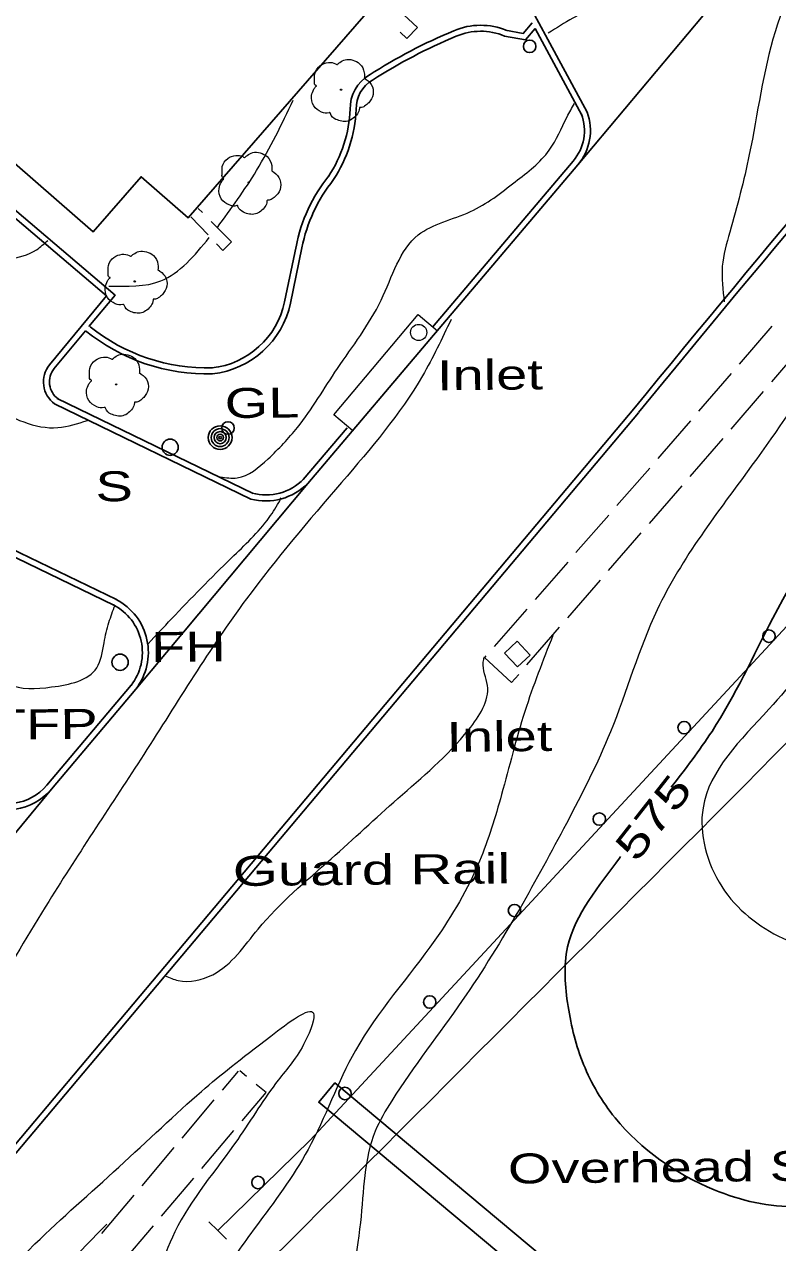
# Model space of a CAD drawing. Extents: x 2361708 to 2370558, y 6977955 to 6991887.
# Drawn here: x 2368899.2 to 2369020, y 6990434.2 to 6990629.5 of the extents above; entities that cross this region are included whole.
import ezdxf
from ezdxf.enums import TextEntityAlignment as Align

# ---------------------------------------------------------------- set-up
doc = ezdxf.new("R2010")
doc.units = 0
doc.header["$LTSCALE"] = 1.9
for name, color, linetype, lineweight in [('11', 7, 'Continuous', 25), ('2', 7, 'Continuous', 25), ('20', 7, 'Continuous', 25), ('21', 7, 'Continuous', 25), ('23', 7, 'Continuous', 25), ('28', 7, 'Continuous', 13), ('29', 7, 'Continuous', 13), ('31', 7, 'Continuous', 13), ('35', 7, 'Continuous', 13), ('4', 7, 'Continuous', 25), ('7', 7, 'Continuous', 25), ('9', 7, 'Continuous', 13)]:
    doc.layers.add(name, color=color, linetype=linetype, lineweight=lineweight)

msp = doc.modelspace()

# ---------------------------------------------------------------- linework, layer by layer
at = {"layer": '11'}
msp.add_lwpolyline([(2368803.061, 6990680.605), (2368887.263, 6990607.323), (2368891.675, 6990612.405), (2368910.239, 6990596.271), (2368917.905, 6990605.094), (2368925.478, 6990598.516), (2368956.5, 6990634.183), (2368949.038, 6990640.673), (2368978.25, 6990674.242), (2368958.133, 6990691.742), (2368936.419, 6990666.784), (2368928.906, 6990673.312), (2368921.191, 6990664.449), (2368845.954, 6990729.906)], close=True, dxfattribs=at)
at = {"layer": '2'}
for p, q in [((2369017.971, 6990642.809), (2368987.911, 6990606.981)), ((2368988.565, 6990614.987), (2368981.082, 6990628.857)), ((2368964.627, 6990580.988), (2368987.175, 6990607.604)), ((2368944.655, 6990555.917), (2368987.911, 6990606.981)), ((2368940.927, 6990585.003), (2368942.763, 6990593.88)), ((2368941.869, 6990584.811), (2368943.705, 6990593.69)), ((2368908.99, 6990580.369), (2368903.958, 6990574.301)), ((2368904.041, 6990568.681), (2368935.488, 6990553.41)), ((2368904.463, 6990569.545), (2368935.91, 6990554.273)), ((2368943.919, 6990556.54), (2368950.96, 6990564.847)), ((2368944.655, 6990555.917), (2368917.077, 6990522.933)), ((2368902.813, 6990507.516), (2368916.341, 6990523.556)), ((2368903.549, 6990506.893), (2368917.077, 6990522.933)), ((2368903.549, 6990506.893), (2368874.918, 6990472.179))]:
    msp.add_line(p, q, dxfattribs=at)
for points in [[(2368989.41, 6990615.446), (2368975.362, 6990641.493), (2368960.799, 6990654.315)], [(2368976.184, 6990627.65), (2368979.55, 6990627.032), (2368981.082, 6990628.857)], [(2368976.354, 6990628.592), (2368979.17, 6990628.079), (2368980.594, 6990629.772)], [(2368887.263, 6990607.323), (2368912.397, 6990585.981), (2368903.222, 6990574.913)], [(2368887.886, 6990608.059), (2368913.746, 6990586.094), (2368909.564, 6990581.064)], [(2368913.951, 6990537.274), (2368882.916, 6990552.269), (2368824.074, 6990603.741), (2368711.364, 6990604.229), (2368623.522, 6990603.912)], [(2368913.529, 6990536.41), (2368882.384, 6990551.464), (2368823.713, 6990602.788), (2368711.363, 6990603.268), (2368623.522, 6990602.952)], [(2368996.914, 6990567.865), (2368920.861, 6990477.417), (2368836.413, 6990376.958), (2368777.799, 6990307.707)], [(2368997.649, 6990567.252), (2368921.597, 6990476.803), (2368837.149, 6990376.334), (2368778.535, 6990307.084)]]:
    msp.add_lwpolyline(points, dxfattribs=at)
for centre, radius, start, end in [((2371141.169, 6988819.351), 2766.791, 136.64719, 140.80479), ((2371141.169, 6988819.351), 2765.831, 136.64719, 140.80479), ((2357902.578, 7001481.989), 15617.856, 315.34492, 316.12114), ((2368972.348, 6990618.451), 10.927, 67.36788, 113.12687), ((2369001.889, 6990547.487), 87.793, 112.66125, 122.67503), ((2369001.889, 6990547.487), 86.833, 112.66125, 122.67503), ((2368972.348, 6990618.451), 9.967, 67.36788, 113.12687), ((2368957.64, 6990616.048), 6.198, 120.13581, 181.80231), ((2368957.64, 6990616.048), 5.238, 120.13581, 181.80231), ((2368929.835, 6990616.938), 21.634, 326.98799, 357.32491), ((2368929.835, 6990616.938), 22.594, 326.98799, 357.32491), ((2368981.547, 6990612.473), 7.446, 319.20201, 20.70764), ((2368981.547, 6990612.473), 8.406, 319.20201, 20.70764), ((2368968.269, 6990588.937), 25.98, 141.16065, 169.05106), ((2368968.269, 6990588.937), 25.02, 141.16065, 169.05106), ((2368927.746, 6990587.819), 13.48, 276.52498, 347.98131), ((2368927.746, 6990587.819), 14.44, 276.52498, 347.98131), ((2368928.518, 6990604.328), 30.867, 230.83015, 271.61276), ((2368928.518, 6990604.328), 29.907, 231.15155, 271.61276), ((2368906.631, 6990572.191), 4.362, 141.3907, 233.58599), ((2368906.631, 6990572.191), 3.402, 141.3907, 233.58599), ((2368937.894, 6990562.623), 8.562, 255.36713, 315.23427), ((2368937.894, 6990562.623), 9.522, 255.36713, 315.23427), ((2368909.514, 6990528.795), 9.569, 322.21872, 62.37943), ((2368909.514, 6990528.795), 8.609, 322.21872, 62.37943), ((2368896.438, 6990512.877), 8.333, 236.84602, 319.91801), ((2368896.438, 6990512.877), 9.293, 236.84602, 319.91801), ((2318071.367, 7041248.644), 71901.899, 314.92877, 315.1113)]:
    msp.add_arc(centre, radius, start, end, dxfattribs=at)
at = {"layer": '20'}
for centre, radius in [((2368930.594, 6990563.253), 1.9), ((2368930.594, 6990563.253), 1.442), ((2368930.594, 6990563.253), 0.973), ((2368931.85, 6990564.785), 1), ((2368930.594, 6990563.253), 0.539), ((2368930.594, 6990563.253), 0.192), ((2368914.556, 6990527.229), 1.3)]:
    msp.add_circle(centre, radius, dxfattribs=at)
at = {"layer": '21'}
msp.add_circle((2368922.579, 6990561.707), 1.3, dxfattribs=at)
at = {"layer": '23'}
msp.add_circle((2368980.209, 6990625.999), 1, dxfattribs=at)
at = {"layer": '28'}
for p, q in [((2368927.741, 6990599.328), (2368927.094, 6990599.982)), ((2368925.877, 6990598.64), (2368928.645, 6990595.756)), ((2369019.038, 6990581.106), (2369013.816, 6990575.046)), ((2369019.013, 6990572.195), (2369024.216, 6990578.265)), ((2369012.51, 6990573.534), (2369007.288, 6990567.474)), ((2369012.505, 6990564.603), (2369017.708, 6990570.673)), ((2369005.957, 6990557.04), (2369011.2, 6990563.09)), ((2368999.454, 6990558.379), (2368994.201, 6990552.348)), ((2368999.408, 6990549.487), (2369004.651, 6990555.528)), ((2368992.885, 6990550.836), (2368987.633, 6990544.805)), ((2368992.86, 6990541.925), (2368998.103, 6990547.975)), ((2368986.317, 6990543.303), (2368981.064, 6990537.273)), ((2368986.312, 6990534.362), (2368991.555, 6990540.412)), ((2368979.749, 6990535.769), (2368974.495, 6990529.74)), ((2368979.774, 6990526.8), (2368985.006, 6990532.85)), ((2368933.461, 6990461.655), (2368930.89, 6990458.591)), ((2368934.83, 6990460.799), (2368933.751, 6990461.698)), ((2368929.605, 6990457.059), (2368924.453, 6990450.939)), ((2368927.65, 6990446.039), (2368932.812, 6990452.149)), ((2368923.167, 6990449.407), (2368918.015, 6990443.288)), ((2368921.202, 6990438.398), (2368926.364, 6990444.507)), ((2368916.73, 6990441.755), (2368911.578, 6990435.636)), ((2368914.745, 6990430.756), (2368919.907, 6990436.866))]:
    msp.add_line(p, q, dxfattribs=at)
for points in [[(2368959.437, 6990628.271), (2368960.517, 6990627.231), (2368962.25, 6990628.998), (2368959.304, 6990631.74)], [(2368930.029, 6990594.31), (2368931.039, 6990593.259), (2368932.395, 6990594.662), (2368929.154, 6990597.911)], [(2369005.982, 6990565.961), (2369001.413, 6990560.637), (2369000.77, 6990559.891)], [(2368973.18, 6990528.237), (2368972.972, 6990527.995), (2368977.32, 6990523.966), (2368978.468, 6990525.287)], [(2368934.107, 6990453.672), (2368937.944, 6990458.218), (2368936.362, 6990459.523)]]:
    msp.add_lwpolyline(points, dxfattribs=at)
at = {"layer": '29'}
for centre in [(2368949.974, 6990619.05), (2368935.155, 6990604.159), (2368916.905, 6990588.304), (2368913.922, 6990571.795)]:
    msp.add_circle(centre, 0.1, dxfattribs=at)
for points in [[(2368946.008, 6990619.623), (2368946.028, 6990619.633), (2368945.948, 6990619.702), (2368945.712, 6990620.33), (2368945.75, 6990621.61), (2368946.637, 6990622.909), (2368947.943, 6990623.392), (2368949.064, 6990623.202), (2368949.296, 6990623.074), (2368949.366, 6990623.075), (2368949.415, 6990623.115), (2368949.763, 6990623.409), (2368950.629, 6990623.857), (2368951.839, 6990623.789), (2368952.955, 6990623.199), (2368953.688, 6990621.776), (2368953.696, 6990620.916)], [(2368953.686, 6990620.936), (2368954.826, 6990619.877), (2368955.111, 6990618.289), (2368954.404, 6990616.963), (2368953.75, 6990616.416), (2368953.081, 6990616.2), (2368952.931, 6990616.189), (2368952.912, 6990616.078), (2368952.591, 6990615.175), (2368951.052, 6990614.01), (2368949.159, 6990614.293), (2368948.26, 6990615.234), (2368948.189, 6990615.363), (2368948.069, 6990615.342), (2368946.858, 6990615.461), (2368945.589, 6990616.459), (2368945.243, 6990618.095), (2368945.613, 6990619.119), (2368945.939, 6990619.562), (2368946.008, 6990619.613)], [(2368931.189, 6990604.731), (2368931.209, 6990604.741), (2368931.129, 6990604.81), (2368930.893, 6990605.438), (2368930.931, 6990606.718), (2368931.818, 6990608.017), (2368933.123, 6990608.5), (2368934.245, 6990608.31), (2368934.477, 6990608.182), (2368934.547, 6990608.183), (2368934.596, 6990608.223), (2368934.944, 6990608.517), (2368935.809, 6990608.966), (2368937.02, 6990608.897), (2368938.136, 6990608.307), (2368938.869, 6990606.884), (2368938.878, 6990606.024)], [(2368938.867, 6990606.044), (2368940.007, 6990604.985), (2368940.292, 6990603.398), (2368939.585, 6990602.071), (2368938.93, 6990601.525), (2368938.262, 6990601.308), (2368938.112, 6990601.296), (2368938.093, 6990601.186), (2368937.772, 6990600.283), (2368936.233, 6990599.119), (2368934.34, 6990599.401), (2368933.441, 6990600.342), (2368933.37, 6990600.471), (2368933.25, 6990600.45), (2368932.039, 6990600.569), (2368930.77, 6990601.567), (2368930.424, 6990603.204), (2368930.794, 6990604.227), (2368931.12, 6990604.67), (2368931.19, 6990604.721)], [(2368912.939, 6990588.876), (2368912.959, 6990588.887), (2368912.879, 6990588.956), (2368912.642, 6990589.584), (2368912.68, 6990590.864), (2368913.569, 6990592.162), (2368914.874, 6990592.645), (2368915.995, 6990592.456), (2368916.227, 6990592.328), (2368916.297, 6990592.328), (2368916.346, 6990592.369), (2368916.694, 6990592.662), (2368917.559, 6990593.111), (2368918.77, 6990593.042), (2368919.885, 6990592.452), (2368920.619, 6990591.03), (2368920.628, 6990590.17)], [(2368920.617, 6990590.19), (2368921.758, 6990589.13), (2368922.043, 6990587.543), (2368921.335, 6990586.216), (2368920.68, 6990585.67), (2368920.012, 6990585.453), (2368919.862, 6990585.442), (2368919.843, 6990585.332), (2368919.522, 6990584.429), (2368917.983, 6990583.264), (2368916.091, 6990583.546), (2368915.191, 6990584.488), (2368915.12, 6990584.617), (2368915, 6990584.596), (2368913.789, 6990584.714), (2368912.52, 6990585.712), (2368912.174, 6990587.349), (2368912.544, 6990588.373), (2368912.87, 6990588.816), (2368912.939, 6990588.866)], [(2368909.956, 6990572.367), (2368909.976, 6990572.377), (2368909.896, 6990572.447), (2368909.66, 6990573.075), (2368909.698, 6990574.355), (2368910.585, 6990575.653), (2368911.89, 6990576.136), (2368913.012, 6990575.947), (2368913.244, 6990575.819), (2368913.314, 6990575.819), (2368913.364, 6990575.86), (2368913.711, 6990576.153), (2368914.576, 6990576.601), (2368915.787, 6990576.533), (2368916.903, 6990575.944), (2368917.636, 6990574.521), (2368917.645, 6990573.661)], [(2368917.634, 6990573.68), (2368918.774, 6990572.621), (2368919.059, 6990571.034), (2368918.352, 6990569.707), (2368917.697, 6990569.161), (2368917.03, 6990568.944), (2368916.88, 6990568.933), (2368916.861, 6990568.823), (2368916.539, 6990567.92), (2368915, 6990566.755), (2368913.107, 6990567.037), (2368912.208, 6990567.978), (2368912.137, 6990568.108), (2368912.017, 6990568.087), (2368910.806, 6990568.205), (2368909.536, 6990569.203), (2368909.191, 6990570.84), (2368909.561, 6990571.863), (2368909.887, 6990572.306), (2368909.957, 6990572.357)]]:
    msp.add_spline(points, degree=3, dxfattribs=at)
at = {"layer": '31', "lineweight": 25}
for points in [[(2369088.686, 6990644.742), (2369081.491, 6990634.793), (2369067.406, 6990613.188), (2369047.405, 6990584.746), (2369032.432, 6990557.712), (2369019.194, 6990534.305), (2369009.436, 6990516.152), (2369002.891, 6990507.188)], [(2368994.777, 6990496.071), (2368994.609, 6990495.839), (2368986.294, 6990481.57), (2368986.365, 6990472.05), (2368988.844, 6990462.743), (2368993.896, 6990454.18), (2369009.786, 6990442.641), (2369023.212, 6990439.969), (2369037.171, 6990443.292), (2369051.308, 6990451.057), (2369056.994, 6990453.551), (2369054.972, 6990449.552), (2369049.111, 6990441.285), (2369037.637, 6990424.865), (2369032.644, 6990416.718), (2369033.637, 6990410.067), (2369039.979, 6990406.757), (2369053.742, 6990403.358), (2369071.707, 6990406.089), (2369090.73, 6990421.661)]]:
    msp.add_spline(points, degree=3, dxfattribs=at)
at = {"layer": '35'}
for points in [[(2369142.131, 6990706.454), (2369132.193, 6990693.679), (2369114.461, 6990671.668), (2369095.193, 6990641.974), (2369078.336, 6990617.423), (2369064.55, 6990594.82), (2369047.526, 6990566.837), (2369036.472, 6990545.18), (2369018.533, 6990519.688), (2369007.993, 6990503.897), (2369011.004, 6990491.245), (2369020.812, 6990482.968), (2369042.265, 6990480.742), (2369066.008, 6990491.099), (2369087.776, 6990506.106), (2369108.873, 6990519.168), (2369106.251, 6990510.873), (2369095.056, 6990495.585), (2369090.948, 6990489.106), (2369090.306, 6990480.859), (2369093.96, 6990472.064), (2369100.283, 6990468.664), (2369121.537, 6990484.057), (2369144.566, 6990505.287), (2369169.56, 6990526.086), (2369196.724, 6990548.916), (2369226.46, 6990573.57), (2369250.046, 6990595.115), (2369253.058, 6990598.144)], [(2369061.565, 6990692.036), (2369052.066, 6990680.285), (2369039.281, 6990662.943), (2369028.55, 6990647.22), (2369019.539, 6990628.333), (2369015.416, 6990608.643), (2369012.285, 6990596.212), (2369011.087, 6990590.721), (2369011.411, 6990585.004)], [(2369003.163, 6990643.598), (2368998.971, 6990639.618), (2368994.302, 6990635.243), (2368990.28, 6990632.275), (2368987.137, 6990630.535), (2368983.199, 6990628.107)], [(2368833.891, 6990631.396), (2368840.245, 6990625.727), (2368851.851, 6990613.596), (2368864.177, 6990603.563), (2368878.689, 6990596.101), (2368889.433, 6990592.583), (2368896.65, 6990591.931), (2368901.156, 6990593.384), (2368902.962, 6990594.882)], [(2368800.158, 6990628.425), (2368811.574, 6990626.774), (2368821.308, 6990623.276), (2368828.124, 6990620.591), (2368836.032, 6990616.646), (2368844.735, 6990606.898), (2368856.024, 6990597.515), (2368867.944, 6990584.998), (2368882.904, 6990574.61), (2368893.845, 6990568.264), (2368904.588, 6990564.856), (2368909.347, 6990566.021)], [(2368930.144, 6990596.951), (2368936.437, 6990606.091), (2368942.32, 6990617.378)], [(2368930.614, 6990556.963), (2368933.316, 6990556.799), (2368938.267, 6990559.836), (2368942.979, 6990564.871), (2368949.39, 6990574.323), (2368956.395, 6990585.31), (2368962.336, 6990595.757), (2368970.711, 6990599.497), (2368977.906, 6990604.285), (2368983.358, 6990609.348), (2368986.208, 6990614.685), (2368987.387, 6990616.846)], [(2369047.828, 6990605.451), (2369038.394, 6990593.231), (2369027.418, 6990575.906), (2369015.841, 6990558.825), (2369000.65, 6990535.639), (2368993.146, 6990516.056), (2368986.096, 6990501.379), (2368978.606, 6990487.716), (2368969.405, 6990472.988), (2368958.108, 6990456.92), (2368955.454, 6990452.025), (2368953.073, 6990437.411), (2368952.752, 6990420.737), (2368959.614, 6990409.992), (2368963.269, 6990401.087), (2368969.023, 6990386.05), (2368979.207, 6990379.327), (2368988.134, 6990377.652), (2368992.144, 6990375.52), (2368991.785, 6990372.277), (2368987.467, 6990362.585), (2368986.816, 6990353.218), (2368988.815, 6990341.807), (2368989.62, 6990331.804), (2368986.922, 6990311.667), (2368979.307, 6990292.194), (2368965.455, 6990270.221), (2368943.017, 6990245.776), (2368913.099, 6990212.86), (2368880.694, 6990176.38), (2368844.682, 6990139.715), (2368811.712, 6990113.21), (2368778.447, 6990087.292), (2368739.578, 6990051.33), (2368711.829, 6990035.275), (2368686.864, 6990022.057), (2368673.109, 6990014.046), (2368669.745, 6990012.454), (2368668.706, 6990013.324), (2368669.63, 6990016.033), (2368674.153, 6990022.016), (2368684.646, 6990033.407), (2368697.173, 6990050.577), (2368697.763, 6990054.743), (2368695.615, 6990054.522), (2368688.933, 6990050.498), (2368671.541, 6990036.962), (2368648.494, 6990028.152), (2368625.507, 6990018.213), (2368603.069, 6990007.409), (2368581.573, 6989999.594), (2368572.511, 6989995.447), (2368567.234, 6989993.027)], [(2368912.742, 6990587.565), (2368921.065, 6990588.384), (2368928.849, 6990595.318)], [(2368975.007, 6990242.79), (2368977.212, 6990239.041), (2368980.344, 6990234.701), (2368984.845, 6990231.453), (2368988.297, 6990232.306), (2368997.733, 6990240.127), (2369004.792, 6990249.684), (2369014.238, 6990262.755), (2369026.599, 6990281.663), (2369036.285, 6990298.917), (2369049.858, 6990320.797), (2369065.658, 6990343.928), (2369079.365, 6990364.3), (2369101.797, 6990393.715), (2369115.12, 6990410.142), (2369135.388, 6990434.726), (2369154.359, 6990456.708), (2369175.603, 6990482.671), (2369195.467, 6990504.392), (2369213.673, 6990524.886), (2369233.782, 6990547.208), (2369250.826, 6990565.772), (2369258.13, 6990573.772), (2369263.297, 6990579.41), (2369267.784, 6990584.914)], [(2368967.606, 6990582.186), (2368963.011, 6990573.142), (2368950.064, 6990556.068), (2368934.8, 6990537.382), (2368918.347, 6990512.444), (2368903.121, 6990488.888), (2368884.755, 6990457.852), (2368873.469, 6990437.443), (2368869.841, 6990426.688), (2368869.607, 6990419.806), (2368870.812, 6990418.177)], [(2368937.295, 6990180.798), (2368941.314, 6990176.667), (2368945.108, 6990173.202), (2368949.849, 6990172.028), (2368956.098, 6990174.317), (2368960.864, 6990178.903), (2368967.964, 6990187.341), (2368980.486, 6990204.011), (2368991.294, 6990221.085), (2369002.356, 6990237.721), (2369015.923, 6990257.061), (2369028.548, 6990276.592), (2369041.722, 6990296.128), (2369052.185, 6990312.709), (2369062.887, 6990328.301), (2369074.163, 6990345.609), (2369084.518, 6990361.929), (2369100.084, 6990382.418), (2369113.698, 6990398.838), (2369127.591, 6990416.431), (2369141.721, 6990435.447), (2369157.025, 6990455.003), (2369173.531, 6990474.471), (2369191.932, 6990495.447), (2369210.576, 6990517.236), (2369225.877, 6990533.982), (2369240.49, 6990549.532), (2369254.835, 6990564.86), (2369264.141, 6990574.799), (2369270.664, 6990581.841)], [(2368919.048, 6990530.202), (2368922.8, 6990534.188), (2368932.398, 6990543.95), (2368938.437, 6990550.417), (2368940.19, 6990553.244), (2368940.366, 6990553.596)], [(2368867.995, 6990526.066), (2368872.936, 6990528.082), (2368879.227, 6990530.083), (2368887.487, 6990529.072), (2368893.114, 6990526.365), (2368896.638, 6990523.768), (2368903.583, 6990523.264), (2368910.815, 6990526.333), (2368911.986, 6990530.355), (2368912.765, 6990533.622), (2368913.749, 6990536.392)], [(2368983.929, 6990531.529), (2368979.435, 6990519.356), (2368975.701, 6990506), (2368972.153, 6990495.326), (2368965.023, 6990482.667), (2368952.28, 6990464.985), (2368944.692, 6990449.112), (2368936.279, 6990436.661), (2368930.708, 6990428.388), (2368926.974, 6990420.332), (2368923.178, 6990407.345), (2368925.818, 6990397.9), (2368929.492, 6990388.004), (2368932.253, 6990381.66), (2368935.154, 6990377.288), (2368935.872, 6990367.074), (2368936.658, 6990350.711), (2368934.899, 6990336.894), (2368925.545, 6990315.203), (2368919.061, 6990298.721), (2368917.665, 6990291.017), (2368922.007, 6990291.848), (2368928.932, 6990298.725), (2368940.303, 6990308.073), (2368954.807, 6990321.422), (2368956.934, 6990318.642), (2368952.658, 6990309.771), (2368947.879, 6990300.145), (2368939.818, 6990283.488), (2368927.075, 6990259.465), (2368910.767, 6990240.319), (2368886.835, 6990212.09), (2368866.726, 6990187.627), (2368845.138, 6990163.161), (2368822.496, 6990139.104), (2368799.648, 6990117.845), (2368778.178, 6990104.05), (2368756.592, 6990085.654), (2368734.588, 6990065.974), (2368713.09, 6990048.828), (2368704.692, 6990045.508), (2368705.15, 6990046.662), (2368709.481, 6990052.884), (2368718.059, 6990061.596), (2368727.733, 6990071.708), (2368736.854, 6990082.166), (2368748.659, 6990097.399), (2368759.795, 6990109.476), (2368764.382, 6990117.239), (2368763.943, 6990120.186), (2368757.319, 6990118.552), (2368746.862, 6990109.793), (2368726.432, 6990091.817), (2368699.934, 6990071.484), (2368679.435, 6990058.628), (2368654.88, 6990046.464), (2368626.237, 6990035.071), (2368603.78, 6990024.176), (2368586.487, 6990016.992), (2368573.437, 6990012.767), (2368565.504, 6990008.782), (2368560.239, 6990006.131), (2368556.575, 6990003.426)], [(2368921.795, 6990476.945), (2368923.883, 6990476.205), (2368929.394, 6990477.128), (2368936.675, 6990484.437), (2368948.368, 6990495.689), (2368959.086, 6990505.392), (2368970.441, 6990516.44), (2368973.435, 6990523.529), (2368972.759, 6990527.223), (2368972.941, 6990528.085)], [(2368789.929, 6990320.343), (2368790.53, 6990320.348), (2368797.873, 6990325.298), (2368807.423, 6990333.68), (2368817.733, 6990344.318), (2368829.52, 6990357.271), (2368840.79, 6990369.879), (2368857.89, 6990388.953), (2368868.503, 6990400.184), (2368882.774, 6990414.871), (2368900.904, 6990433.954), (2368914.357, 6990446.283), (2368927.592, 6990458.41), (2368938.738, 6990467.296), (2368945.543, 6990470.961), (2368944.236, 6990466.448), (2368939.885, 6990460.207), (2368933.405, 6990450.725), (2368923.326, 6990435.878), (2368917.886, 6990422.216), (2368911.041, 6990411.13), (2368905.079, 6990401.823), (2368900.974, 6990394.023), (2368900.322, 6990384.766), (2368901.314, 6990374.025), (2368904.437, 6990367.355), (2368904.31, 6990359.763), (2368903.563, 6990354.106), (2368901.129, 6990347.222), (2368896.475, 6990339.217), (2368894.175, 6990318.195), (2368888.579, 6990298.791), (2368874.725, 6990269.767), (2368859.183, 6990244.758), (2368839.662, 6990217.401), (2368811.187, 6990186.269), (2368782.802, 6990157.217), (2368754.567, 6990130.256), (2368727.088, 6990107.924), (2368698.455, 6990089.211), (2368672.208, 6990074.11), (2368648.698, 6990060.265), (2368628.721, 6990050.445), (2368613.068, 6990044.306), (2368603.074, 6990040.52), (2368593.252, 6990034.387), (2368582.867, 6990026.477), (2368572.981, 6990018.563), (2368564.602, 6990014.263), (2368560.596, 6990012.755), (2368556.513, 6990009.896), (2368554.167, 6990007.363), (2368553.067, 6990006.373)], [(2368672.622, 6990193.42), (2368677.499, 6990196.877), (2368689.448, 6990206.571), (2368704.224, 6990219.602), (2368717.195, 6990232.226), (2368732.475, 6990247.012), (2368743.676, 6990258.509), (2368759.297, 6990275.259), (2368769.621, 6990286.508), (2368783.909, 6990302.554), (2368801.545, 6990320.823), (2368816.251, 6990336.034), (2368827.604, 6990348.413), (2368841.891, 6990363.499), (2368853.954, 6990376.915), (2368873.879, 6990397.545), (2368883.733, 6990407.64), (2368895.263, 6990419.25), (2368903.392, 6990427.818), (2368912.434, 6990437.134)]]:
    msp.add_spline(points, degree=3, dxfattribs=at)
at = {"layer": '4'}
for points in [[(2368930.195, 6990436.114), (2368945.027, 6990450.585), (2369055.557, 6990569.873)], [(2368931.608, 6990434.707), (2368930.195, 6990436.114), (2368928.781, 6990437.52)]]:
    msp.add_lwpolyline(points, dxfattribs=at)
for centre in [(2369018.566, 6990531.422), (2369004.973, 6990516.751), (2368991.379, 6990502.081), (2368977.786, 6990487.411), (2368964.192, 6990472.74), (2368950.599, 6990458.07), (2368936.654, 6990443.813)]:
    msp.add_circle(centre, 1, dxfattribs=at)
at = {"layer": '7'}
msp.add_lwpolyline([(2369018.195, 6990401.839), (2368949, 6990459.784), (2368946.389, 6990456.669), (2369015.585, 6990398.724)], close=True, dxfattribs=at)
at = {"layer": '9'}
msp.add_lwpolyline([(2368951.835, 6990564.335), (2368948.79, 6990566.897), (2368962.308, 6990582.996), (2368965.423, 6990580.376)], dxfattribs=at)
msp.add_lwpolyline([(2368976.185, 6990528.706), (2368978.256, 6990526.475), (2368980.299, 6990528.365), (2368978.227, 6990530.595)], close=True, dxfattribs=at)
msp.add_circle((2368962.415, 6990580.117), 1.3, dxfattribs=at)

# ---------------------------------------------------------------- texts
at = {"layer": '20', "width": 1.4}
for s, p in [('  GL', (2368926.345, 6990566.333)), ('  FH', (2368914.547, 6990527.219)), ('  TFP', (2368889.024, 6990514.775))]:
    msp.add_text(s, height=4.8, rotation=0.545, dxfattribs=at).set_placement(p)
at = {"layer": '21', "width": 1.4}
msp.add_text('  S', height=4.8, rotation=0.545, dxfattribs=at).set_placement((2368905.64, 6990552.975))
at = {"layer": '31', "width": 1.4}
msp.add_text(' 575 ', height=4.8, rotation=51.938, dxfattribs=at).set_placement((2369001.923, 6990500.862), align=Align.CENTER)
at = {"layer": '4', "width": 1.45}
msp.add_text('Guard Rail', height=4.8, rotation=0.545, dxfattribs=at).set_placement((2368932.639, 6990491.349))
at = {"layer": '7', "width": 1.4}
msp.add_text('Overhead Sign', height=4.8, rotation=0.545, dxfattribs=at).set_placement((2368976.735, 6990443.627))
at = {"layer": '9', "width": 1.4}
for p in [(2368965.364, 6990570.835), (2368966.876, 6990512.856)]:
    msp.add_text('Inlet', height=4.8, rotation=0.545, dxfattribs=at).set_placement(p)

doc.saveas('drawing.dxf')
